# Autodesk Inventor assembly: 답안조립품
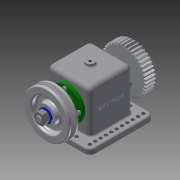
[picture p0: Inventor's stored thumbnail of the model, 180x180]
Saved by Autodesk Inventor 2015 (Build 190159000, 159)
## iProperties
Created: 2018-11
Part Number: 답안조립품
Document SubType Name: Assembly
Designer: now
Author: now
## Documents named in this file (13)
- C:\Users\now\Desktop\481108V1017\답안조립품.iam
- C:\Users\now\Desktop\481108V1017\V벨트풀리.ipt
- C:\Users\now\Desktop\481108V1017\너트 M12x1.25.ipt
- C:\Users\now\Desktop\481108V1017\베어링 6203.ipt
- C:\Users\now\Desktop\481108V1017\본체.ipt
- C:\Users\now\Desktop\481108V1017\볼트 M4.ipt
- C:\Users\now\Desktop\481108V1017\부시.ipt
- C:\Users\now\Desktop\481108V1017\스퍼기어.ipt
- C:\Users\now\Desktop\481108V1017\오일 실 26 38 8.ipt
- C:\Users\now\Desktop\481108V1017\와셔 12x24.ipt
- C:\Users\now\Desktop\481108V1017\축.ipt
- C:\Users\now\Desktop\481108V1017\커버.ipt
- C:\Users\now\Desktop\481108V1017\키 5x5x12.ipt
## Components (1 placed, 1 different names)
1. V벨트풀리:1 — 각도:3
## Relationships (1: Angle 1)
- 각도:3 [Angle]: V벨트풀리:1
